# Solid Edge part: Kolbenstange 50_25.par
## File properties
Username: ahadarics
Dokumentum tartalom típus: 0
Author: ahadarics
Last saved by: ahadarics
Revision: 78
Sűrűség: 0,000 kg/m^3
Pontosság: 0,990
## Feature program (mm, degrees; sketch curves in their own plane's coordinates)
base feature "unnamed BaseFeature 1"
thread "unnamed Thread 1"
chamfer "Letörés_1"  SetBackValue2 = 20 deg
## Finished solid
Body 1: solid body, 21 faces, 32 edges, 14 vertices.
  Faces by surface: plane 8, cylinder 5, cone 4, torus 4
  Edges by curve: circle 17, line 9, curve on surface 4, ellipse 2
Bounding box of the edges (mm; curved faces can reach further): 50.000 x 50.000 x 169.000, from (-25, -25, -86.5) to (25, 25, 82.5).
Cylindrical faces by radius (mm): R6.75 x1, R8 x1, R9.75 x1, R10 x1, R25 x1
Conical faces (half-angle, radius in mm at the cone's reference point): 20 deg R8 x1, 30 deg R9.875 x1, 45 deg R24.25 x1, 60 deg R7.375 x1
Toroidal faces (ring radius, tube radius in mm): R7.15 r0.4 x2, R8.55 r1.2 x2
Planar faces by outward normal: +x 1, +z 3, -x 1, -z 1, oblique 2
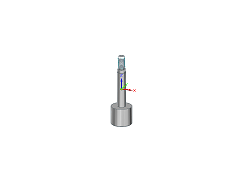
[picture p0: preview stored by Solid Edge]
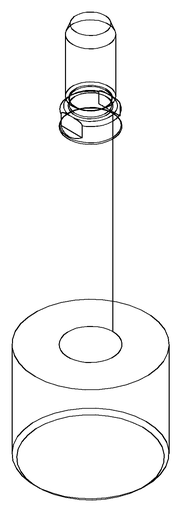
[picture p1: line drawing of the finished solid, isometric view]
